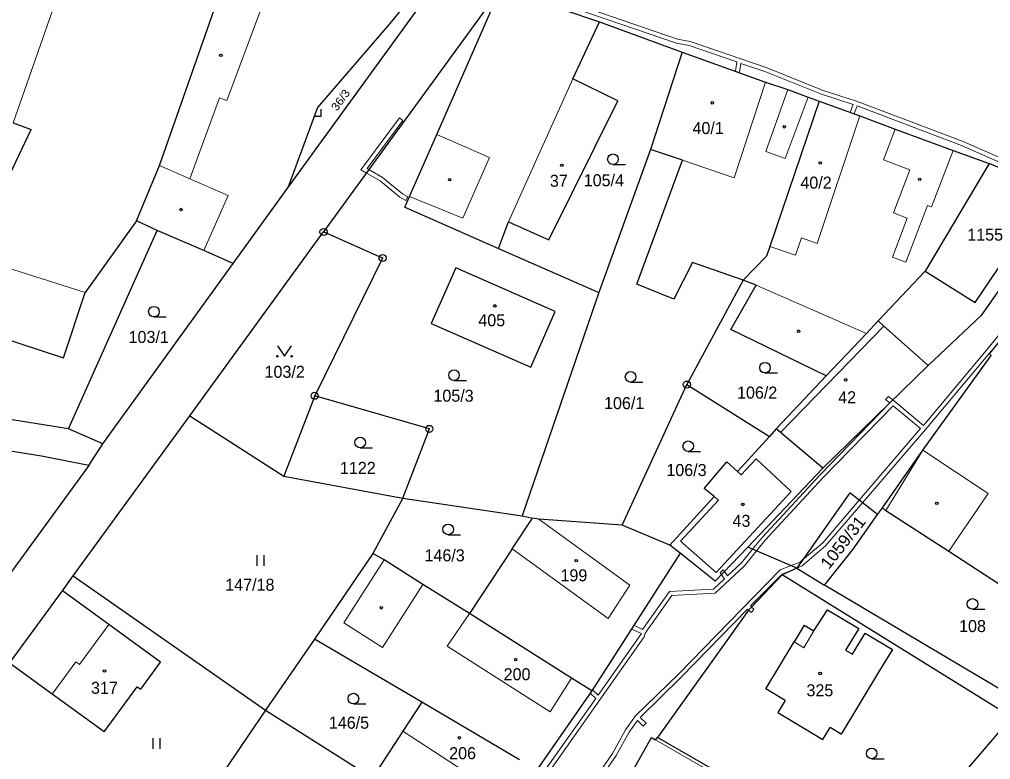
# Model space of a CAD drawing. Extents: x -694609 to -690140, y -1033292 to -1029794.
# Drawn here: x -692824.6 to -692687.4, y -1031423.4 to -1031318.8 of the extents above; entities that cross this region are included whole.
import ezdxf
from ezdxf.enums import TextEntityAlignment as Align

# ---------------------------------------------------------------- set-up
doc = ezdxf.new("R2010")
doc.units = 0
doc.header["$LTSCALE"] = 0.68
for name, color, linetype, lineweight in [('1', 7, 'Continuous', 25), ('13', 7, 'Continuous', 13), ('3', 7, 'Continuous', 25), ('4', 7, 'Continuous', 13), ('5', 7, 'Continuous', 25), ('8', 7, 'Continuous', 25)]:
    doc.layers.add(name, color=color, linetype=linetype, lineweight=lineweight)
doc.layers.add('2', color=7, linetype='Continuous')

msp = doc.modelspace()

# ---------------------------------------------------------------- linework, layer by layer
at = {"layer": '1'}
for p, q in [((-692766.01, -1031311.66), (-692772.28, -1031319.36)), ((-692786.72, -1031342.61), (-692764.55, -1031312.11)), ((-692804.83, -1031339.46), (-692796.07, -1031314.41)), ((-692756.6, -1031314.4), (-692781.66, -1031348.84)), ((-692765.65, -1031335.04), (-692756.6, -1031314.4)), ((-692756.6, -1031314.4), (-692742.67, -1031319.12)), ((-692772.28, -1031319.36), (-692782.52, -1031331.24)), ((-692746.4, -1031327.2), (-692742.67, -1031319.12)), ((-692742.67, -1031319.12), (-692730.94, -1031323.4)), ((-692730.94, -1031323.4), (-692735.44, -1031337.16)), ((-692730.94, -1031323.4), (-692719.16, -1031327.65)), ((-692740.07, -1031330.32), (-692746.4, -1031327.2)), ((-692719.16, -1031327.65), (-692716.02, -1031328.71)), ((-692716.02, -1031328.71), (-692713.17, -1031329.78)), ((-692749.79, -1031349.94), (-692740.07, -1031330.32)), ((-692711.61, -1031330.33), (-692718.55, -1031350.89)), ((-692713.17, -1031329.78), (-692711.61, -1031330.33)), ((-692711.61, -1031330.33), (-692705.84, -1031332.41)), ((-692782.52, -1031331.24), (-692786.72, -1031342.61)), ((-692705.84, -1031332.41), (-692700.87, -1031334.31)), ((-692825.53, -1031333.39), (-692822.98, -1031334.36)), ((-692831.53, -1031352.24), (-692822.98, -1031334.36)), ((-692769.5, -1031343.82), (-692765.65, -1031335.04)), ((-692700.87, -1031334.31), (-692692.67, -1031337.3)), ((-692735.44, -1031337.16), (-692742.76, -1031357.41)), ((-692730.9, -1031338.7), (-692735.44, -1031337.16)), ((-692692.67, -1031337.3), (-692687.56, -1031339.16)), ((-692737.39, -1031356.2), (-692730.9, -1031338.7)), ((-692687.56, -1031339.16), (-692696.62, -1031354.37)), ((-692678.77, -1031342.85), (-692687.56, -1031339.16)), ((-692808.1, -1031347.25), (-692804.83, -1031339.46)), ((-692794.41, -1031353.31), (-692786.72, -1031342.61)), ((-692689.54, -1031358.81), (-692678.77, -1031342.85)), ((-692770.16, -1031345.34), (-692769.5, -1031343.82)), ((-692676.85, -1031343.68), (-692688.71, -1031360.64)), ((-692770.16, -1031345.34), (-692756.94, -1031351.16)), ((-692808.1, -1031347.25), (-692815.33, -1031357.4)), ((-692805.16, -1031348.61), (-692808.1, -1031347.25)), ((-692756.94, -1031351.16), (-692755.51, -1031347.42)), ((-692755.51, -1031347.42), (-692749.79, -1031349.94)), ((-692817.73, -1031376.68), (-692805.16, -1031348.61)), ((-692798.58, -1031351.46), (-692805.16, -1031348.61)), ((-692800.56, -1031374.81), (-692781.66, -1031348.84)), ((-692773.31, -1031352.52), (-692781.66, -1031348.84)), ((-692794.41, -1031353.31), (-692798.58, -1031351.46)), ((-692756.94, -1031351.16), (-692742.76, -1031357.41)), ((-692718.55, -1031350.89), (-692719.02, -1031352.27)), ((-692773.31, -1031352.52), (-692782.91, -1031372)), ((-692719.02, -1031352.27), (-692722.33, -1031355.66)), ((-692812.86, -1031378.78), (-692794.41, -1031353.31)), ((-692762.97, -1031353.89), (-692766.45, -1031361.79)), ((-692748.9, -1031360.06), (-692762.97, -1031353.89)), ((-692729.51, -1031353.16), (-692732.16, -1031358.35)), ((-692722.33, -1031355.66), (-692729.51, -1031353.16)), ((-692696.62, -1031354.37), (-692703.25, -1031361.4)), ((-692696.62, -1031354.37), (-692689.54, -1031358.81)), ((-692722.33, -1031355.66), (-692730.3, -1031370.41)), ((-692720.5, -1031356.35), (-692722.33, -1031355.66)), ((-692732.16, -1031358.35), (-692737.39, -1031356.2)), ((-692724.06, -1031362.61), (-692720.5, -1031356.35)), ((-692818.41, -1031366.65), (-692815.33, -1031357.4)), ((-692742.76, -1031357.41), (-692753.6, -1031388.99)), ((-692834.78, -1031361.26), (-692818.41, -1031366.65)), ((-692752.36, -1031367.96), (-692748.9, -1031360.06)), ((-692688.71, -1031360.64), (-692696.17, -1031367.74)), ((-692766.45, -1031361.79), (-692752.36, -1031367.96)), ((-692710.61, -1031369.19), (-692724.06, -1031362.61)), ((-692703.25, -1031361.4), (-692704.92, -1031363.17)), ((-692704.92, -1031363.17), (-692710.61, -1031369.19)), ((-692696.17, -1031367.74), (-692711.1, -1031382.23)), ((-692710.61, -1031369.19), (-692717.67, -1031376.67)), ((-692739.45, -1031390.31), (-692730.3, -1031370.41)), ((-692730.3, -1031370.41), (-692718.63, -1031377.75)), ((-692817.73, -1031376.68), (-692846.59, -1031372.09)), ((-692782.91, -1031372), (-692787.25, -1031383.36)), ((-692766.7, -1031376.68), (-692782.91, -1031372)), ((-692817.04, -1031397.46), (-692800.56, -1031374.81)), ((-692800.56, -1031374.81), (-692787.25, -1031383.36)), ((-692821.53, -1031380.52), (-692843.95, -1031377.07)), ((-692812.86, -1031378.78), (-692817.73, -1031376.68)), ((-692770.44, -1031386.47), (-692766.7, -1031376.68)), ((-692718.63, -1031377.75), (-692723.15, -1031382.68)), ((-692717.67, -1031376.67), (-692718.63, -1031377.75)), ((-692717.05, -1031377.2), (-692717.67, -1031376.67)), ((-692711.1, -1031382.23), (-692717.05, -1031377.2)), ((-692814.81, -1031381.84), (-692812.86, -1031378.78)), ((-692814.81, -1031381.84), (-692821.53, -1031380.52)), ((-692702.66, -1031387.82), (-692696.94, -1031379.7)), ((-692814.81, -1031381.84), (-692843.63, -1031421.29)), ((-692727.83, -1031385.09), (-692724.63, -1031381.33)), ((-692724.63, -1031381.33), (-692723.15, -1031382.68)), ((-692721.7, -1031393.38), (-692711.1, -1031382.23)), ((-692787.25, -1031383.36), (-692770.44, -1031386.47)), ((-692726.43, -1031386.26), (-692727.83, -1031385.09)), ((-692707.28, -1031385.74), (-692714.76, -1031396.35)), ((-692703.33, -1031388.77), (-692707.28, -1031385.74)), ((-692770.44, -1031386.47), (-692774.67, -1031394.28)), ((-692770.44, -1031386.47), (-692753.6, -1031388.99)), ((-692726.43, -1031386.26), (-692732.69, -1031393.1)), ((-692703.33, -1031388.77), (-692702.66, -1031387.82)), ((-692702.66, -1031387.82), (-692702.15, -1031388.23)), ((-692702.15, -1031388.23), (-692693.28, -1031393.98)), ((-692755, -1031393.64), (-692752.1, -1031389.31)), ((-692753.6, -1031388.99), (-692752.1, -1031389.31)), ((-692751.24, -1031389.44), (-692752.1, -1031389.31)), ((-692739.45, -1031390.31), (-692751.24, -1031389.44)), ((-692706.78, -1031393.68), (-692703.33, -1031388.77)), ((-692732.69, -1031393.1), (-692739.45, -1031390.31)), ((-692755, -1031393.64), (-692761.04, -1031402.76)), ((-692731.26, -1031394.26), (-692732.69, -1031393.1)), ((-692726.29, -1031398.21), (-692721.7, -1031393.38)), ((-692714.76, -1031396.35), (-692721.7, -1031393.38)), ((-692710.84, -1031398.79), (-692706.78, -1031393.68)), ((-692693.28, -1031393.98), (-692683.35, -1031400.43)), ((-692774.67, -1031394.28), (-692782.93, -1031406.4)), ((-692773.09, -1031395.18), (-692774.67, -1031394.28)), ((-692767.63, -1031398.69), (-692773.09, -1031395.18)), ((-692731.26, -1031394.26), (-692743.74, -1031413.72)), ((-692726.29, -1031398.21), (-692731.26, -1031394.26)), ((-692714.76, -1031396.35), (-692716.84, -1031397.3)), ((-692714.76, -1031396.35), (-692710.84, -1031398.79)), ((-692818.56, -1031399.55), (-692817.04, -1031397.46)), ((-692817.04, -1031397.46), (-692789.88, -1031416.45)), ((-692716.84, -1031397.3), (-692721.15, -1031401.86)), ((-692686.06, -1031416.42), (-692716.84, -1031397.3)), ((-692826.04, -1031409.79), (-692818.56, -1031399.55)), ((-692812.01, -1031404.32), (-692818.56, -1031399.55)), ((-692761.04, -1031402.76), (-692767.63, -1031398.69)), ((-692684.23, -1031414.56), (-692710.84, -1031398.79)), ((-692721.57, -1031402.29), (-692734.45, -1031420.29)), ((-692721.57, -1031402.29), (-692721.15, -1031401.86)), ((-692712.36, -1031405.25), (-692710.43, -1031402.24)), ((-692710.43, -1031402.24), (-692706, -1031404.9)), ((-692746.6, -1031411.9), (-692761.04, -1031402.76)), ((-692804.7, -1031409.64), (-692812.01, -1031404.32)), ((-692713.73, -1031404.42), (-692715.12, -1031406.8)), ((-692713.73, -1031404.42), (-692712.36, -1031405.25)), ((-692706, -1031404.9), (-692707.85, -1031407.96)), ((-692782.93, -1031406.4), (-692789.88, -1031416.45)), ((-692767.77, -1031415.32), (-692782.93, -1031406.4)), ((-692706.87, -1031408.55), (-692705.07, -1031405.55)), ((-692705.07, -1031405.55), (-692701.24, -1031407.87)), ((-692719.14, -1031413.42), (-692715.12, -1031406.8)), ((-692707.85, -1031407.96), (-692706.87, -1031408.55)), ((-692701.24, -1031407.87), (-692703.09, -1031410.82)), ((-692820.03, -1031414.16), (-692826.04, -1031409.79)), ((-692807.5, -1031413.48), (-692804.7, -1031409.64)), ((-692743.74, -1031413.72), (-692746.6, -1031411.9)), ((-692703.09, -1031410.82), (-692708.49, -1031419.82)), ((-692812.65, -1031419.53), (-692807.99, -1031413.13)), ((-692807.99, -1031413.13), (-692807.5, -1031413.48)), ((-692716.39, -1031415.07), (-692719.14, -1031413.42)), ((-692812.65, -1031419.53), (-692820.03, -1031414.16)), ((-692743.74, -1031413.72), (-692751.52, -1031424.89)), ((-692767.77, -1031415.32), (-692770.44, -1031419.41)), ((-692753.94, -1031423.46), (-692767.77, -1031415.32)), ((-692716.39, -1031415.07), (-692717.42, -1031416.78)), ((-692789.88, -1031416.45), (-692796.87, -1031426.72)), ((-692789.88, -1031416.45), (-692774.74, -1031425.99)), ((-692717.42, -1031416.78), (-692711.06, -1031420.6)), ((-692701.34, -1031437.24), (-692684.27, -1031417.34)), ((-692711.06, -1031420.6), (-692710.03, -1031418.89)), ((-692708.49, -1031419.82), (-692710.03, -1031418.89)), ((-692770.44, -1031419.41), (-692774.74, -1031425.99)), ((-692734.72, -1031420.66), (-692734.45, -1031420.29)), ((-692712.18, -1031433.11), (-692734.45, -1031420.29))]:
    msp.add_line(p, q, dxfattribs=at)
for points in [[(-692696.94, -1031379.7), (-692687.27, -1031366.28), (-692687.51, -1031366.09), (-692673.46, -1031348.86)], [(-692737.89, -1031424.94), (-692735.3, -1031420.32), (-692734.72, -1031420.66)]]:
    msp.add_lwpolyline(points, dxfattribs=at)
at = {"layer": '13'}
for points in [[(-692747.34, -1031316.81), (-692731.78, -1031322.14), (-692729.99, -1031322.5), (-692723.23, -1031324.8), (-692723.44, -1031326.11), (-692722.86, -1031326.31), (-692722.65, -1031325), (-692719.27, -1031326.16), (-692711.25, -1031329.38), (-692706.79, -1031330.8), (-692707.19, -1031331.92), (-692706.63, -1031332.13), (-692706.22, -1031331), (-692691.48, -1031336.62), (-692677.69, -1031342.7), (-692677.11, -1031342.94), (-692677.07, -1031342.28), (-692691.26, -1031336.06), (-692706.3, -1031330.33), (-692711.05, -1031328.82), (-692719.07, -1031325.6), (-692729.83, -1031321.92), (-692731.62, -1031321.56), (-692747.14, -1031316.25)], [(-692671.97, -1031346.02), (-692687.69, -1031365.27), (-692696.85, -1031376.18), (-692701.17, -1031372.59), (-692701.59, -1031373), (-692711.46, -1031383.16), (-692719.61, -1031391.98), (-692721, -1031393.68), (-692722.58, -1031395.61), (-692724.55, -1031397.47), (-692724.99, -1031396.85), (-692725.42, -1031397.29), (-692725, -1031397.88), (-692726.53, -1031399.33), (-692732.73, -1031399.66), (-692736.55, -1031405.05), (-692737.8, -1031404.45), (-692738.13, -1031404.97), (-692736.73, -1031405.62), (-692742.83, -1031414.3), (-692743.63, -1031413.55), (-692743.74, -1031413.72), (-692743.98, -1031414.06), (-692743.18, -1031414.8), (-692750.99, -1031425.83)], [(-692705.94, -1031386.76), (-692705.47, -1031387.13), (-692696.57, -1031376.77), (-692687.26, -1031365.69)], [(-692821.78, -1031533.86), (-692814.94, -1031522.92), (-692812.73, -1031520.08), (-692794.48, -1031492.55), (-692788.19, -1031483.36), (-692787.79, -1031482.62), (-692780.53, -1031471.44), (-692778.71, -1031469.03), (-692767.21, -1031451.27), (-692764.08, -1031446.79), (-692756.04, -1031434.68), (-692753.23, -1031430.1), (-692736.34, -1031406.09), (-692736.18, -1031405.56), (-692732.41, -1031400.24), (-692726.28, -1031399.91), (-692722.14, -1031396.02), (-692720.43, -1031393.92), (-692719.16, -1031392.37), (-692711.07, -1031383.61), (-692701.14, -1031373.4), (-692697.25, -1031376.64), (-692705.94, -1031386.76)], [(-692743.48, -1031427.51), (-692740.31, -1031422.87), (-692738.45, -1031419.55), (-692737.27, -1031417.92), (-692736.48, -1031418.7), (-692736.06, -1031418.28), (-692736.88, -1031417.46), (-692731.09, -1031411.8), (-692721.73, -1031402.15), (-692721.57, -1031402.29), (-692721.15, -1031401.86), (-692721.31, -1031401.71), (-692716.84, -1031397.24), (-692714.76, -1031396.35), (-692713.98, -1031395.24), (-692714.28, -1031395.5), (-692715.56, -1031396.01), (-692717.11, -1031396.62), (-692731.48, -1031411.34)], [(-692731.48, -1031411.34), (-692737.54, -1031417.26), (-692738.96, -1031419.23), (-692740.83, -1031422.56), (-692743.96, -1031427.15), (-692748.24, -1031432.48), (-692753.7, -1031440.49), (-692757.22, -1031445.99), (-692759.8, -1031449.66), (-692768.34, -1031462.88), (-692769.39, -1031464.78), (-692778.6, -1031479.36), (-692782.17, -1031484.44), (-692788.53, -1031493.82), (-692793.95, -1031502.2), (-692813.14, -1031530.87)]]:
    msp.add_lwpolyline(points, dxfattribs=at)
for points in [[(-692770.93, -1031332.71), (-692776.39, -1031340.06), (-692775.6, -1031340.51), (-692775.25, -1031340.03), (-692775.51, -1031339.88), (-692770.45, -1031333.07)], [(-692775.6, -1031340.51), (-692773.64, -1031341.63), (-692770.85, -1031343.93), (-692770.02, -1031344.39), (-692769.73, -1031343.86), (-692770.51, -1031343.43), (-692773.3, -1031341.13), (-692775.25, -1031340.03)], [(-692701.59, -1031373), (-692701.17, -1031372.59), (-692701.79, -1031372.08), (-692702.21, -1031372.51)], [(-692705.47, -1031387.13), (-692705.94, -1031386.76), (-692711.1, -1031392.77), (-692713.98, -1031395.24), (-692714.76, -1031396.35), (-692713.98, -1031396.02), (-692710.68, -1031393.19)], [(-692725.42, -1031397.29), (-692724.99, -1031396.85), (-692725.17, -1031396.6), (-692725.59, -1031397.05)], [(-692721.15, -1031401.86), (-692721.57, -1031402.29), (-692721.18, -1031402.64), (-692720.83, -1031402.17)]]:
    msp.add_lwpolyline(points, close=True, dxfattribs=at)
at = {"layer": '3'}
for p, q in [((-692740.743, -1031339.31), (-692738.993, -1031339.31)), ((-692805.633, -1031360.86), (-692803.883, -1031360.86)), ((-692719.253, -1031368.77), (-692717.503, -1031368.77)), ((-692763.213, -1031369.84), (-692761.463, -1031369.84)), ((-692738.253, -1031370.07), (-692736.503, -1031370.07)), ((-692776.483, -1031379.35), (-692774.733, -1031379.35)), ((-692730.103, -1031379.88), (-692728.353, -1031379.88)), ((-692764.033, -1031391.64), (-692762.283, -1031391.64)), ((-692791.061, -1031396.04), (-692791.061, -1031394.54)), ((-692790.06, -1031396.04), (-692790.06, -1031394.54)), ((-692689.923, -1031402.18), (-692688.173, -1031402.18)), ((-692777.433, -1031415.56), (-692775.683, -1031415.56)), ((-692805.761, -1031421.89), (-692805.761, -1031420.39)), ((-692804.76, -1031421.89), (-692804.76, -1031420.39)), ((-692704.173, -1031423.31), (-692702.423, -1031423.31))]:
    msp.add_line(p, q, dxfattribs=at)
for points in [[(-692783.001, -1031332.46), (-692782, -1031332.46), (-692782, -1031331.46)], [(-692788.17, -1031364.919), (-692787.17, -1031366.42), (-692786.17, -1031364.919)]]:
    msp.add_lwpolyline(points, dxfattribs=at)
for centre, radius in [((-692740.7429, -1031338.5598), 0.75), ((-692805.6329, -1031360.1098), 0.75), ((-692788.17, -1031366.4195), 0.1), ((-692786.17, -1031366.4195), 0.1), ((-692719.2529, -1031368.0198), 0.75), ((-692763.2129, -1031369.0898), 0.75), ((-692738.2529, -1031369.3198), 0.75), ((-692776.4829, -1031378.5998), 0.75), ((-692730.1029, -1031379.1298), 0.75), ((-692764.0329, -1031390.8898), 0.75), ((-692689.9229, -1031401.4298), 0.75), ((-692777.4329, -1031414.8098), 0.75), ((-692704.1729, -1031422.5598), 0.75)]:
    msp.add_circle(centre, radius, dxfattribs=at)
at = {"layer": '4'}
for p, q in [((-692825.53, -1031333.39), (-692819.34, -1031315.7)), ((-692790.23, -1031316.62), (-692795.34, -1031330.27)), ((-692755.51, -1031347.42), (-692746.4, -1031327.2)), ((-692719.16, -1031327.65), (-692723.62, -1031341.17)), ((-692716.02, -1031328.71), (-692719.15, -1031337.48)), ((-692795.34, -1031330.27), (-692796.38, -1031329.89)), ((-692716.41, -1031338.43), (-692713.17, -1031329.78)), ((-692705.84, -1031332.41), (-692711.87, -1031350.45)), ((-692765.65, -1031335.04), (-692758.21, -1031338.29)), ((-692702.52, -1031338.62), (-692700.87, -1031334.31)), ((-692719.15, -1031337.48), (-692716.41, -1031338.43)), ((-692692.67, -1031337.3), (-692695.72, -1031345.28)), ((-692761.97, -1031346.9), (-692758.21, -1031338.29)), ((-692723.62, -1031341.17), (-692730.9, -1031338.7)), ((-692698.78, -1031340.05), (-692702.52, -1031338.62)), ((-692804.83, -1031339.46), (-692800.55, -1031341.33)), ((-692701.1, -1031346.12), (-692698.78, -1031340.05)), ((-692795.16, -1031343.69), (-692798.58, -1031351.46)), ((-692769.5, -1031343.82), (-692761.97, -1031346.9)), ((-692699.14, -1031346.87), (-692701.1, -1031346.12)), ((-692696.26, -1031345.08), (-692699.33, -1031353.11)), ((-692695.72, -1031345.28), (-692696.26, -1031345.08)), ((-692701.25, -1031352.38), (-692699.14, -1031346.87)), ((-692714.1, -1031349.69), (-692714.93, -1031352.12)), ((-692711.87, -1031350.45), (-692714.1, -1031349.69)), ((-692714.93, -1031352.12), (-692718.55, -1031350.89)), ((-692831.53, -1031352.24), (-692815.33, -1031357.4)), ((-692699.33, -1031353.11), (-692701.25, -1031352.38)), ((-692720.5, -1031356.35), (-692704.92, -1031363.17)), ((-692717.05, -1031377.2), (-692702.47, -1031362.17)), ((-692703.25, -1031361.4), (-692702.47, -1031362.17)), ((-692702.47, -1031362.17), (-692696.17, -1031367.74)), ((-692702.15, -1031388.23), (-692696.94, -1031379.7)), ((-692696.94, -1031379.7), (-692687.72, -1031385.81)), ((-692720.51, -1031380.91), (-692722.62, -1031383.17)), ((-692720.51, -1031380.91), (-692715.53, -1031385.53)), ((-692723.15, -1031382.68), (-692722.62, -1031383.17)), ((-692715.53, -1031385.53), (-692726.17, -1031396.96)), ((-692687.72, -1031385.81), (-692693.28, -1031393.98)), ((-692731.2, -1031392.55), (-692725.84, -1031386.75)), ((-692725.84, -1031386.75), (-692726.43, -1031386.26)), ((-692738.36, -1031398.79), (-692751.24, -1031389.44)), ((-692726.17, -1031396.96), (-692731.2, -1031392.55)), ((-692755, -1031393.64), (-692741.4, -1031403.5)), ((-692773.09, -1031395.18), (-692778.79, -1031404.08)), ((-692773.33, -1031407.59), (-692767.63, -1031398.69)), ((-692738.36, -1031398.79), (-692741.4, -1031403.5)), ((-692764.2, -1031407.39), (-692761.04, -1031402.76)), ((-692816.15, -1031410), (-692812.01, -1031404.32)), ((-692778.79, -1031404.08), (-692773.33, -1031407.59)), ((-692713.74, -1031407.61), (-692712.36, -1031405.25)), ((-692764.2, -1031407.39), (-692749.64, -1031416.67)), ((-692713.74, -1031407.61), (-692715.12, -1031406.8)), ((-692816.65, -1031409.63), (-692820.03, -1031414.16)), ((-692816.65, -1031409.63), (-692816.15, -1031410)), ((-692746.6, -1031411.9), (-692749.64, -1031416.67)), ((-692770.44, -1031419.41), (-692757, -1031428.16))]:
    msp.add_line(p, q, dxfattribs=at)
for points in [[(-692796.38, -1031329.89), (-692800.55, -1031341.33), (-692795.16, -1031343.69)], [(-692734.72, -1031420.66), (-692718.36, -1031430.08), (-692718.26, -1031429.9), (-692712.32, -1031433.32), (-692712.18, -1031433.11)]]:
    msp.add_lwpolyline(points, dxfattribs=at)
at = {"layer": '5'}
for centre in [(-692796.1768, -1031323.8792), (-692726.7068, -1031330.5792), (-692716.5268, -1031333.9692), (-692747.9668, -1031339.4292), (-692711.4468, -1031339.0992), (-692763.8168, -1031341.4392), (-692697.3868, -1031341.3992), (-692801.8168, -1031345.6692), (-692757.4468, -1031359.2892), (-692714.5068, -1031362.8692), (-692707.8368, -1031369.7392), (-692722.3868, -1031387.3592), (-692694.9668, -1031387.1992), (-692745.9368, -1031395.3192), (-692773.4968, -1031401.9692), (-692754.5068, -1031409.2892), (-692812.6168, -1031410.9092), (-692711.4568, -1031411.2592), (-692762.4568, -1031420.3492)]:
    msp.add_circle(centre, 0.175, dxfattribs=at)
at = {"layer": '8'}
for centre, radius in [((-692781.66, -1031348.8399), 0.5), ((-692781.66, -1031348.8399), 0.0303), ((-692773.31, -1031352.5199), 0.5), ((-692773.31, -1031352.5199), 0.0303), ((-692730.3, -1031370.4099), 0.5), ((-692730.3, -1031370.4099), 0.0303), ((-692782.91, -1031371.9999), 0.5), ((-692782.91, -1031371.9999), 0.0303), ((-692766.7, -1031376.6799), 0.5), ((-692766.7, -1031376.6799), 0.0303)]:
    msp.add_circle(centre, radius, dxfattribs=at)

# ---------------------------------------------------------------- texts
at = {"layer": '2'}
for s, height, rotation, width, p in [('36/3', 1.14, 54, 1.1, (-692778.7948, -1031330.517)), ('1059/31', 1.7, 52, 1.05, (-692707.5567, -1031393.2343))]:
    msp.add_text(s, height=height, rotation=rotation, dxfattribs=dict(at, width=width)).set_placement(p, align=Align.CENTER)
for s, p in [('40/1', (-692727.289, -1031334.995)), ('105/4', (-692742.03, -1031342.375)), ('37', (-692748.399, -1031342.455)), ('40/2', (-692712.039, -1031342.715)), ('1155', (-692688.13, -1031350.065)), ('405', (-692757.879, -1031362.165)), ('103/1', (-692806.37, -1031364.535)), ('103/2', (-692787.15, -1031369.455)), ('106/2', (-692720.36, -1031372.395)), ('105/3', (-692763.28, -1031372.835)), ('106/1', (-692739.16, -1031373.885)), ('42', (-692707.639, -1031373.055)), ('1122', (-692776.81, -1031383.045)), ('106/3', (-692730.35, -1031383.345)), ('43', (-692722.579, -1031390.525)), ('146/3', (-692764.54, -1031395.405)), ('199', (-692746.269, -1031398.235)), ('147/18', (-692792.07, -1031399.565)), ('108', (-692689.919, -1031405.405)), ('200', (-692754.299, -1031412.215)), ('317', (-692812.629, -1031414.135)), ('325', (-692711.499, -1031414.485)), ('146/5', (-692778.06, -1031419.065)), ('206', (-692761.999, -1031423.375))]:
    msp.add_text(s, height=1.7, dxfattribs=at).set_placement(p, align=Align.CENTER)

doc.saveas('drawing.dxf')
